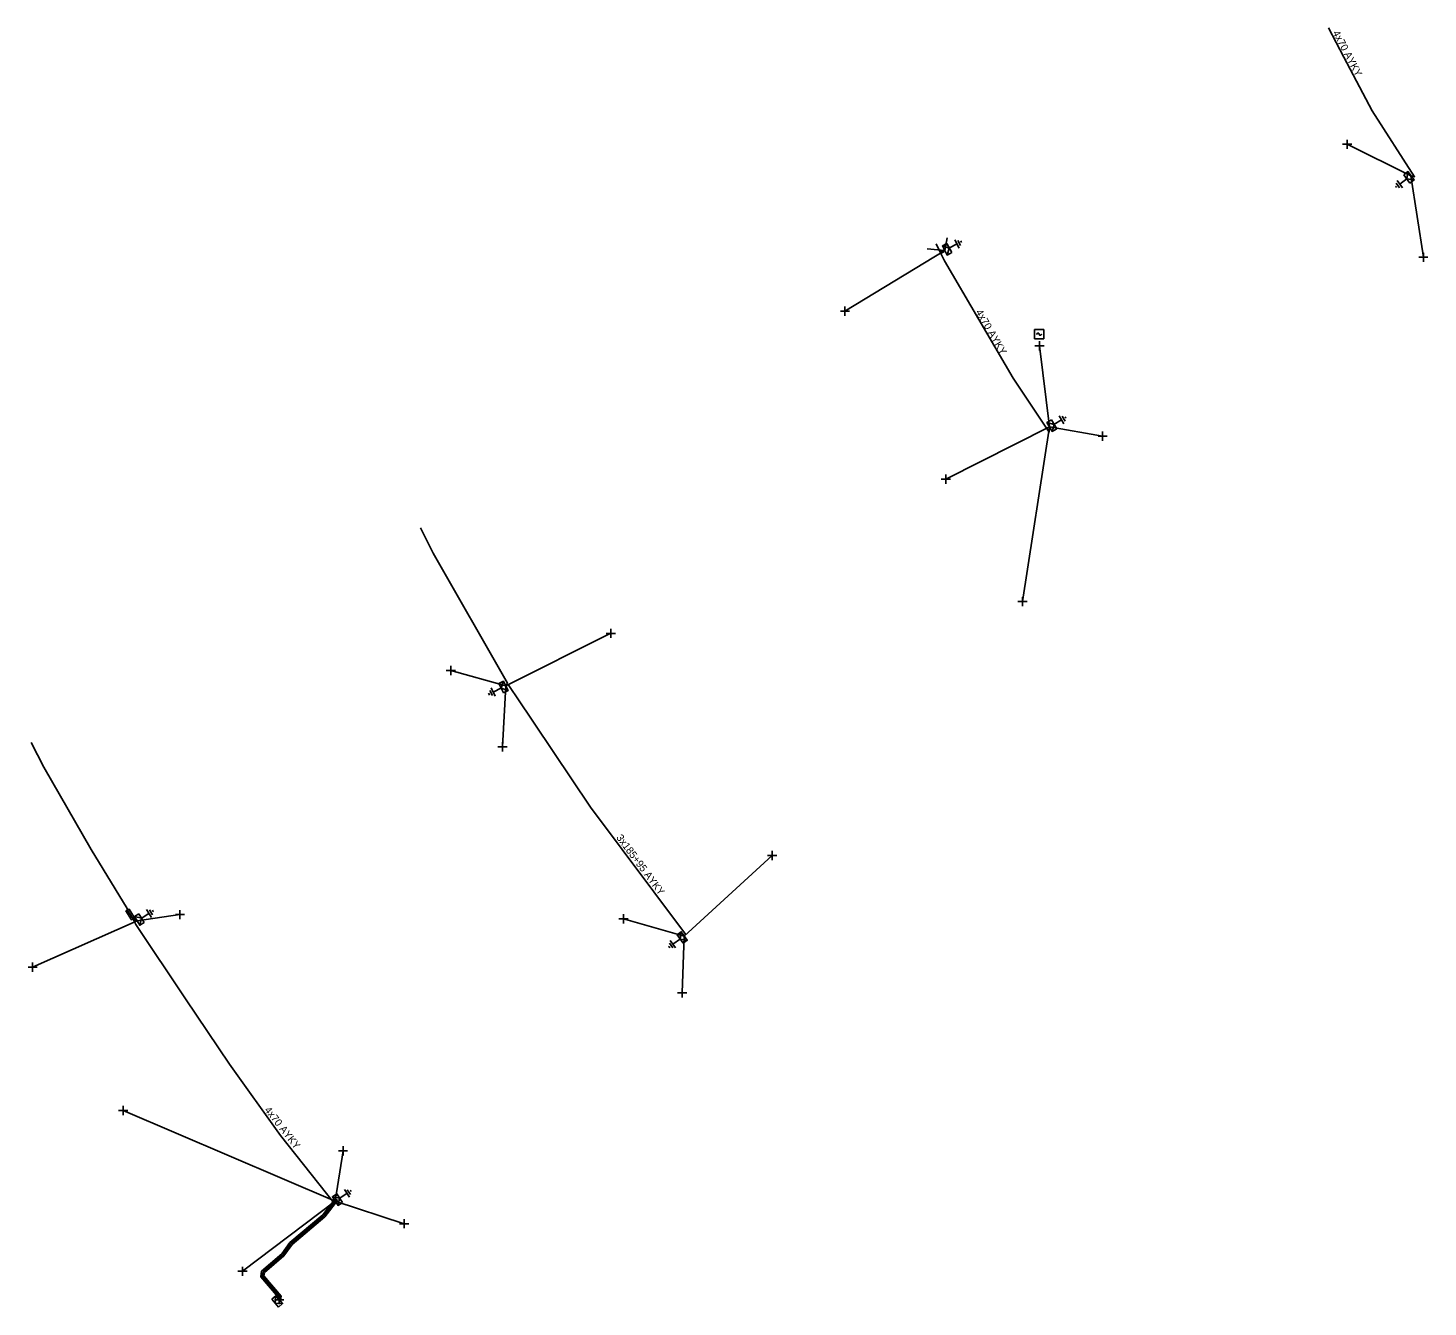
# Model space of a CAD drawing. Extents: x -540247 to -537390, y -1183890 to -1180355.
# Drawn here: x -538671 to -538481.3, y -1180645.1 to -1180471.8 of the extents above; entities that cross this region are included whole.
import ezdxf

# ---------------------------------------------------------------- set-up
doc = ezdxf.new("R2010")
doc.units = 0
for name, color, linetype in [('Vrstva 1', 7, 'Continuous'), ('Vrstva 14', 7, 'Continuous'), ('Vrstva 15', 7, 'Continuous'), ('Vrstva 20', 7, 'Continuous'), ('Vrstva 31', 7, 'Continuous'), ('Vrstva 34', 7, 'Continuous'), ('Vrstva 5', 7, 'Continuous'), ('Vrstva 52', 7, 'Continuous'), ('Vrstva 59', 7, 'Continuous'), ('Vrstva 6', 7, 'Continuous'), ('Vrstva 9', 7, 'Continuous')]:
    doc.layers.add(name, color=color, linetype=linetype)

# ---------------------------------------------------------------- blocks, each defined once
blk = doc.blocks.new('NN800')
at = {"layer": 'Vrstva 1'}
for points in [[(-0.44, 0.44), (0.44, -0.44)], [(-0.44, -0.44), (0.44, 0.44)]]:
    blk.add_lwpolyline(points, dxfattribs=at)
blk = doc.blocks.new('NN630')
at = {"layer": 'Vrstva 9'}
for points in [[(0, -0.7), (-0.7, 0)], [(-0.7, -0.7), (-0.7, 0), (0.7, 0), (0.7, -0.7)], [(-0.7, -0.7), (0.7, -0.7)], [(0, -0.7), (0.7, 0)]]:
    blk.add_lwpolyline(points, dxfattribs=at)
blk = doc.blocks.new('NN810')
at = {"layer": 'Vrstva 14'}
for points in [[(0.63, -1.89), (-0.62, -1.89)], [(0, -0.64), (0, -1.89)], [(0.39, -2.2), (-0.4, -2.2)], [(0, -2.52), (-0.12, -2.52)], [(0.14, -2.52), (0, -2.52)]]:
    blk.add_lwpolyline(points, dxfattribs=at)
blk = doc.blocks.new('NN740')
at = {"layer": 'Vrstva 1'}
for points in [[(0.62, 0.62), (-0.63, 0.62)], [(-0.63, 0.62), (-0.63, -0.63)], [(0, 0), (0, 0.01), (0, 0.03), (-0.01, 0.05), (-0.01, 0.06), (-0.02, 0.08), (-0.03, 0.09), (-0.04, 0.1), (-0.05, 0.11), (-0.06, 0.12), (-0.08, 0.13), (-0.09, 0.14), (-0.11, 0.14), (-0.12, 0.15), (-0.14, 0.15), (-0.15, 0.15), (-0.17, 0.15), (-0.18, 0.15), (-0.2, 0.15), (-0.21, 0.14), (-0.23, 0.13), (-0.24, 0.12), (-0.26, 0.11), (-0.27, 0.1), (-0.28, 0.09), (-0.29, 0.08), (-0.29, 0.06), (-0.3, 0.05), (-0.3, 0.03), (-0.31, 0.02), (-0.31, 0), (-0.31, 0)], [(0.62, -0.63), (0.62, 0.62)], [(-0.63, -0.63), (0.62, -0.63)], [(0, 0), (0, -0.02), (0, -0.03), (0.01, -0.05), (0.01, -0.06), (0.02, -0.08), (0.03, -0.09), (0.04, -0.1), (0.05, -0.11), (0.06, -0.12), (0.07, -0.13), (0.09, -0.14), (0.1, -0.15), (0.12, -0.15), (0.13, -0.15), (0.15, -0.15), (0.16, -0.15), (0.18, -0.15), (0.19, -0.15), (0.21, -0.14), (0.22, -0.14), (0.24, -0.13), (0.25, -0.12), (0.26, -0.11), (0.27, -0.09), (0.28, -0.08), (0.29, -0.07), (0.29, -0.05), (0.3, -0.04), (0.3, -0.02), (0.3, -0.01), (0.3, -0.01)]]:
    blk.add_lwpolyline(points, dxfattribs=at)

msp = doc.modelspace()

# ---------------------------------------------------------------- linework, layer by layer
at = {"layer": 'Vrstva 20'}
for points in [[(-538657.77, -1180591.45), (-538657.35, -1180591.19), (-538656.62, -1180592.38), (-538657.04, -1180592.64)], [(-538635.26, -1180636.67), (-538636.36, -1180638.21), (-538639.01, -1180640.47), (-538639.08, -1180640.9), (-538636.73, -1180643.66), (-538636.81, -1180644.17), (-538637.21, -1180644.11), (-538637.15, -1180643.78), (-538639.5, -1180641.02), (-538639.39, -1180640.27), (-538636.66, -1180637.93), (-538635.56, -1180636.39), (-538631.1, -1180632.61), (-538629.43, -1180630.45), (-538629.11, -1180630.69), (-538630.82, -1180632.89)]]:
    msp.add_lwpolyline(points, close=True, dxfattribs=at)
at = {"layer": 'Vrstva 5'}
for points in [[(-538494.84, -1180471.77), (-538492.74, -1180475.73), (-538488.88, -1180482.98), (-538483.15, -1180491.93), (-538483.64, -1180491.8)], [(-538532.61, -1180525.85), (-538532.67, -1180526.55), (-538537.55, -1180519.21), (-538546.87, -1180503.33), (-538547.37, -1180502.32), (-538546.9, -1180502.07), (-538546.82, -1180501.92), (-538546.99, -1180501.9), (-538547.45, -1180502.14), (-538548, -1180501.04)], [(-538582.12, -1180594.84), (-538581.94, -1180594.6), (-538594.83, -1180577.39), (-538604.95, -1180562.28), (-538605.46, -1180561.58), (-538605.98, -1180560.76), (-538606.17, -1180560.95), (-538606.31, -1180560.94), (-538606.31, -1180560.8), (-538606.08, -1180560.58), (-538616.14, -1180542.95), (-538617.88, -1180539.53)], [(-538629.41, -1180630.77), (-538629.55, -1180631.07), (-538636.81, -1180621.87), (-538643.75, -1180612.19), (-538649.72, -1180603.36), (-538656.43, -1180593.3), (-538656.76, -1180592.66), (-538656.48, -1180592.79), (-538656.27, -1180592.78), (-538656.4, -1180592.61), (-538656.93, -1180592.35), (-538657.56, -1180591.32), (-538657.6, -1180591.13), (-538662.48, -1180583.1), (-538668.88, -1180571.97), (-538670.64, -1180568.59)]]:
    msp.add_lwpolyline(points, dxfattribs=at)
at = {"layer": 'Vrstva 52'}
msp.add_lwpolyline([(-538629.41, -1180630.77), (-538629.5, -1180630.86), (-538630.96, -1180632.75), (-538635.41, -1180636.53), (-538636.51, -1180638.07), (-538639.2, -1180640.37), (-538639.29, -1180640.96), (-538636.94, -1180643.72), (-538637.01, -1180644.14)], dxfattribs=at)
at = {"layer": 'Vrstva 59'}
for points in [[(-538483.64, -1180491.8), (-538492.29, -1180487.53)], [(-538483.64, -1180491.8), (-538481.96, -1180502.85)], [(-538546.82, -1180501.92), (-538549.22, -1180501.72)], [(-538546.82, -1180501.92), (-538546.49, -1180500.22)], [(-538546.82, -1180501.92), (-538560.34, -1180510.15)], [(-538532.61, -1180525.85), (-538533.98, -1180514.86)], [(-538532.61, -1180525.85), (-538546.67, -1180532.92)], [(-538532.61, -1180525.85), (-538536.29, -1180549.52)], [(-538532.61, -1180525.85), (-538525.43, -1180527.1)], [(-538606.31, -1180560.94), (-538592.08, -1180553.81)], [(-538606.31, -1180560.94), (-538613.75, -1180558.86)], [(-538606.31, -1180560.94), (-538606.76, -1180569.19)], [(-538582.12, -1180594.84), (-538570.21, -1180583.93)], [(-538656.27, -1180592.78), (-538670.42, -1180599.07)], [(-538656.27, -1180592.78), (-538650.46, -1180591.94)], [(-538582.12, -1180594.84), (-538590.35, -1180592.51)], [(-538582.12, -1180594.84), (-538582.4, -1180602.55)], [(-538629.41, -1180630.77), (-538658.14, -1180618.5)], [(-538629.41, -1180630.77), (-538628.36, -1180623.95)], [(-538629.41, -1180630.77), (-538641.99, -1180640.28)], [(-538629.41, -1180630.77), (-538620.08, -1180633.83)]]:
    msp.add_lwpolyline(points, dxfattribs=at)

# ---------------------------------------------------------------- block references
at = {"layer": 'Vrstva 15'}
for p, rotation in [((-538483.64, -1180491.8), -53.60530824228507), ((-538546.82, -1180501.92), 117.71850268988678), ((-538532.61, -1180525.85), 120.52268051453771), ((-538606.31, -1180560.94), -63.86697789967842), ((-538656.27, -1180592.78), 121.52684163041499), ((-538582.12, -1180594.84), -54.18360829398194), ((-538629.41, -1180630.77), 123.37476397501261)]:
    msp.add_blockref('NN810', p, dxfattribs=dict(at, rotation=rotation))
at = {"layer": 'Vrstva 31'}
for p, rotation in [((-538483.64, -1180491.8), -53.60530837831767), ((-538546.82, -1180501.92), 117.71850275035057), ((-538532.61, -1180525.85), 120.5226805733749), ((-538606.31, -1180560.94), -63.86697777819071), ((-538656.27, -1180592.78), 121.52684163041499), ((-538582.12, -1180594.84), -54.18360829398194), ((-538629.41, -1180630.77), 123.40349724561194), ((-538637.01, -1180644.14), -49.38278887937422)]:
    msp.add_blockref('NN630', p, dxfattribs=dict(at, rotation=rotation))
at = {"layer": 'Vrstva 34'}
for p, rotation in [((-538492.29, -1180487.53), 45), ((-538481.96, -1180502.85), 45), ((-538560.34, -1180510.15), 45), ((-538533.98, -1180514.86), 45), ((-538525.43, -1180527.1), 45.00000009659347), ((-538546.67, -1180532.92), 45), ((-538536.29, -1180549.52), 45), ((-538592.08, -1180553.82), 45.00000009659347), ((-538613.75, -1180558.86), 45), ((-538606.76, -1180569.19), 45.00000009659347), ((-538570.21, -1180583.93), 45), ((-538650.46, -1180591.94), 45), ((-538590.35, -1180592.51), 45), ((-538670.42, -1180599.07), 44.99999995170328), ((-538582.4, -1180602.55), 45), ((-538658.14, -1180618.5), 44.99999995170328), ((-538628.36, -1180623.95), 45), ((-538620.08, -1180633.83), 45), ((-538641.99, -1180640.28), 45), ((-538637.01, -1180644.14), 45)]:
    msp.add_blockref('NN800', p, dxfattribs=dict(at, rotation=rotation))
msp.add_blockref('NN740', (-538534.03, -1180513.27), dxfattribs=at)

# ---------------------------------------------------------------- texts
at = {"layer": 'Vrstva 6'}
for s, rotation, p in [('4x70 AYKY', 297.928, (-538494.29, -1180472.41)), ('4x70 AYKY', 300.409, (-538542.68, -1180510.26)), ('3x185+95 AYKY', 306.833, (-538591.39, -1180581.52)), ('4x70 AYKY', 308.278, (-538639.07, -1180618.45))]:
    msp.add_text(s, height=1, rotation=rotation, dxfattribs=at).set_placement(p)

doc.saveas('drawing.dxf')
